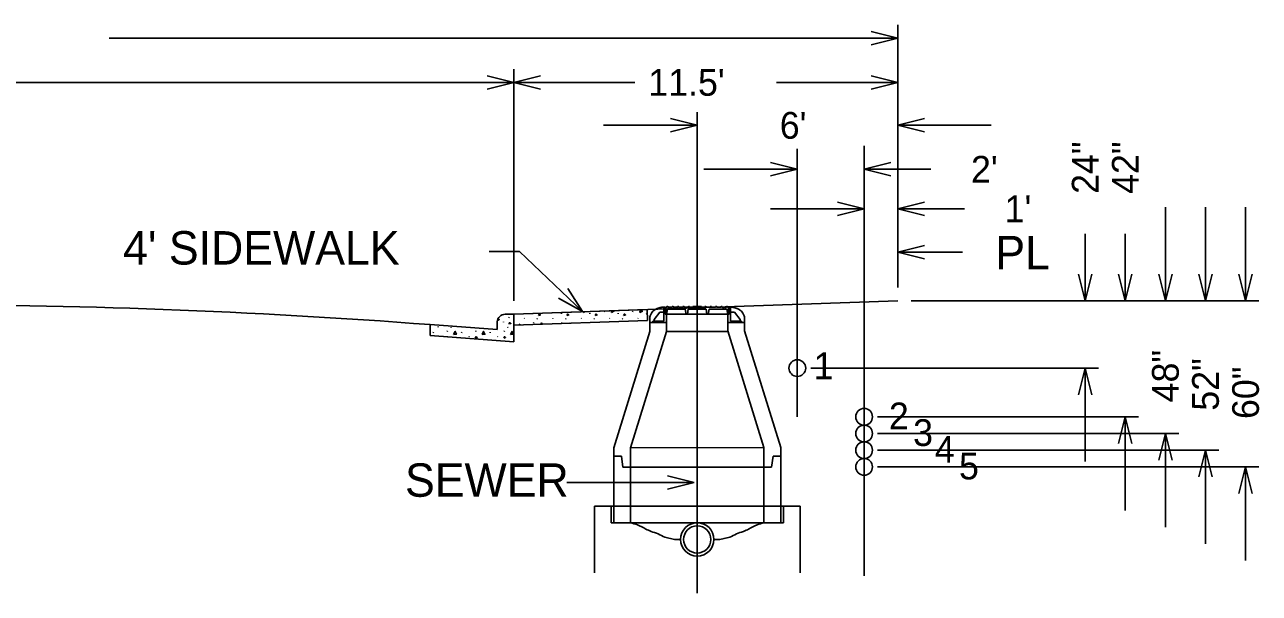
# Model space of a CAD drawing. Extents: x 524397 to 525117, y 3701341 to 3701821.
# Drawn here: x 524798.7 to 524872.7, y 3701503 to 3701537 of the extents above; entities that cross this region are included whole.
import ezdxf

# ---------------------------------------------------------------- set-up
doc = ezdxf.new("R2010")
doc.units = 0
doc.layers.add('Level 11', color=7, linetype='Continuous')

msp = doc.modelspace()

# ---------------------------------------------------------------- linework, layer by layer
at = {"layer": 'Level 11'}
for p, q in [((524851.022, 3701521.302), (524851.022, 3701537.038)), ((524849.421, 3701536.638), (524851.022, 3701536.238)), ((524803.793, 3701536.238), (524851.022, 3701536.238)), ((524851.022, 3701536.238), (524849.421, 3701535.838)), ((524828.022, 3701520.499), (524828.022, 3701534.384)), ((524851.022, 3701521.302), (524851.022, 3701534.384)), ((524793.673, 3701533.584), (524828.022, 3701533.584)), ((524826.421, 3701533.984), (524828.022, 3701533.584)), ((524828.022, 3701533.584), (524826.421, 3701533.183)), ((524828.022, 3701533.584), (524829.623, 3701533.984)), ((524835.28, 3701533.584), (524828.022, 3701533.584)), ((524829.623, 3701533.183), (524828.022, 3701533.584)), ((524843.764, 3701533.584), (524851.022, 3701533.584)), ((524849.421, 3701533.984), (524851.022, 3701533.584)), ((524851.022, 3701533.584), (524849.421, 3701533.183)), ((524837.407, 3701531.413), (524839.008, 3701531.013)), ((524839.008, 3701531.802), (524839.008, 3701502.983)), ((524851.022, 3701531.013), (524852.623, 3701531.413)), ((524833.405, 3701531.013), (524839.008, 3701531.013)), ((524839.008, 3701531.013), (524837.407, 3701530.613)), ((524856.626, 3701531.013), (524851.022, 3701531.013)), ((524852.623, 3701530.613), (524851.022, 3701531.013)), ((524845.008, 3701529.609), (524845.008, 3701513.548)), ((524849.008, 3701529.785), (524849.008, 3701504.024)), ((524839.405, 3701528.381), (524845.008, 3701528.381)), ((524843.407, 3701528.781), (524845.008, 3701528.381)), ((524845.008, 3701528.381), (524843.407, 3701527.981)), ((524849.008, 3701528.381), (524850.609, 3701528.781)), ((524853.011, 3701528.381), (524849.008, 3701528.381)), ((524850.609, 3701527.981), (524849.008, 3701528.381)), ((524843.405, 3701526.012), (524849.008, 3701526.012)), ((524847.407, 3701526.413), (524849.008, 3701526.012)), ((524849.008, 3701526.012), (524847.407, 3701525.612)), ((524851.022, 3701526.012), (524852.623, 3701526.413)), ((524855.025, 3701526.012), (524851.022, 3701526.012)), ((524852.623, 3701525.612), (524851.022, 3701526.012)), ((524867.055, 3701526.106), (524867.055, 3701520.502)), ((524869.456, 3701526.106), (524869.456, 3701520.502)), ((524871.858, 3701526.106), (524871.858, 3701520.502)), ((524862.252, 3701524.505), (524862.252, 3701520.502)), ((524864.653, 3701524.505), (524864.653, 3701520.502)), ((524851.022, 3701523.408), (524852.623, 3701523.808)), ((524828.357, 3701523.464), (524826.552, 3701523.464)), ((524832.135, 3701519.853), (524828.357, 3701523.464)), ((524851.022, 3701523.408), (524854.898, 3701523.408)), ((524852.623, 3701523.008), (524851.022, 3701523.408)), ((524862.252, 3701520.502), (524861.852, 3701522.103)), ((524862.652, 3701522.103), (524862.252, 3701520.502)), ((524864.653, 3701520.502), (524864.253, 3701522.103)), ((524865.054, 3701522.103), (524864.653, 3701520.502)), ((524867.055, 3701520.502), (524866.655, 3701522.103)), ((524867.455, 3701522.103), (524867.055, 3701520.502)), ((524869.456, 3701520.502), (524869.056, 3701522.103)), ((524869.856, 3701522.103), (524869.456, 3701520.502)), ((524871.858, 3701520.502), (524871.457, 3701522.103)), ((524872.258, 3701522.103), (524871.858, 3701520.502)), ((524831.254, 3701521.248), (524832.135, 3701519.853)), ((524828.022, 3701519.699), (524851.022, 3701520.502)), ((524832.135, 3701519.853), (524830.701, 3701520.669)), ((524837.009, 3701520.118), (524837.009, 3701520.118)), ((524837.009, 3701520.118), (524837.093, 3701520.118)), ((524837.009, 3701519.826), (524837.009, 3701520.118)), ((524837.093, 3701519.701), (524837.093, 3701520.118)), ((524837.134, 3701520.118), (524837.134, 3701519.701)), ((524837.177, 3701520.118), (524837.134, 3701520.118)), ((524837.176, 3701519.701), (524837.227, 3701519.993)), ((524837.177, 3701520.118), (524837.192, 3701520.159)), ((524837.192, 3701520.159), (524837.254, 3701520.159)), ((524838.29, 3701519.993), (524837.227, 3701519.993)), ((524837.269, 3701520.118), (524837.254, 3701520.159)), ((524837.501, 3701520.118), (524837.269, 3701520.118)), ((524837.501, 3701520.118), (524837.516, 3701520.159)), ((524837.516, 3701520.159), (524837.575, 3701520.159)), ((524837.59, 3701520.118), (524837.575, 3701520.159)), ((524837.817, 3701520.118), (524837.59, 3701520.118)), ((524837.817, 3701520.118), (524837.832, 3701520.159)), ((524837.832, 3701520.159), (524837.9, 3701520.159)), ((524837.915, 3701520.118), (524837.9, 3701520.159)), ((524838.144, 3701520.118), (524837.915, 3701520.118)), ((524838.144, 3701520.118), (524838.159, 3701520.159)), ((524838.159, 3701520.159), (524838.224, 3701520.159)), ((524838.24, 3701520.118), (524838.224, 3701520.159)), ((524838.467, 3701520.118), (524838.24, 3701520.118)), ((524838.342, 3701519.701), (524838.29, 3701519.993)), ((524838.425, 3701519.701), (524838.477, 3701519.993)), ((524838.467, 3701520.118), (524838.482, 3701520.159)), ((524839.54, 3701519.993), (524838.477, 3701519.993)), ((524838.482, 3701520.159), (524838.54, 3701520.159)), ((524838.555, 3701520.118), (524838.54, 3701520.159)), ((524838.742, 3701520.118), (524838.555, 3701520.118)), ((524838.742, 3701520.118), (524838.757, 3701520.159)), ((524838.757, 3701520.159), (524839.008, 3701520.159)), ((524839.259, 3701520.159), (524839.008, 3701520.159)), ((524839.275, 3701520.118), (524839.259, 3701520.159)), ((524839.461, 3701520.118), (524839.275, 3701520.118)), ((524839.461, 3701520.118), (524839.476, 3701520.159)), ((524839.535, 3701520.159), (524839.476, 3701520.159)), ((524839.55, 3701520.118), (524839.535, 3701520.159)), ((524839.591, 3701519.701), (524839.54, 3701519.993)), ((524839.777, 3701520.118), (524839.55, 3701520.118)), ((524839.674, 3701519.701), (524839.725, 3701519.993)), ((524840.789, 3701519.993), (524839.725, 3701519.993)), ((524839.777, 3701520.118), (524839.792, 3701520.159)), ((524839.857, 3701520.159), (524839.792, 3701520.159)), ((524839.873, 3701520.118), (524839.857, 3701520.159)), ((524840.101, 3701520.118), (524839.873, 3701520.118)), ((524840.101, 3701520.118), (524840.116, 3701520.159)), ((524840.185, 3701520.159), (524840.116, 3701520.159)), ((524840.199, 3701520.118), (524840.185, 3701520.159)), ((524840.426, 3701520.118), (524840.199, 3701520.118)), ((524840.426, 3701520.118), (524840.441, 3701520.159)), ((524840.5, 3701520.159), (524840.441, 3701520.159)), ((524840.515, 3701520.118), (524840.5, 3701520.159)), ((524840.747, 3701520.118), (524840.515, 3701520.118)), ((524840.57, 3701520.118), (524840.57, 3701519.993)), ((524840.695, 3701520.118), (524840.695, 3701519.993)), ((524840.747, 3701520.118), (524840.762, 3701520.159)), ((524840.825, 3701520.159), (524840.762, 3701520.159)), ((524840.841, 3701519.701), (524840.789, 3701519.993)), ((524840.84, 3701520.118), (524840.825, 3701520.159)), ((524840.881, 3701520.118), (524840.84, 3701520.118)), ((524840.881, 3701520.118), (524840.881, 3701519.701)), ((524840.924, 3701519.701), (524840.923, 3701520.118)), ((524841.007, 3701520.118), (524840.923, 3701520.118)), ((524841.007, 3701519.826), (524841.007, 3701520.118)), ((524851.823, 3701520.502), (524863.052, 3701520.502)), ((524851.823, 3701520.502), (524865.454, 3701520.502)), ((524851.823, 3701520.502), (524867.855, 3701520.502)), ((524851.823, 3701520.502), (524870.257, 3701520.502)), ((524851.823, 3701520.502), (524872.658, 3701520.502)), ((524827.411, 3701519.251), (524827.415, 3701519.219)), ((524828.022, 3701519.699), (524827.509, 3701519.699)), ((524827.509, 3701519.699), (524827.522, 3701519.699)), ((524827.728, 3701519.486), (524827.743, 3701519.517)), ((524828.022, 3701519.699), (524836.017, 3701519.978)), ((524828.022, 3701518.037), (524828.022, 3701519.699)), ((524828.022, 3701519.039), (524828.022, 3701519.699)), ((524836.041, 3701519.319), (524828.022, 3701519.039)), ((524828.655, 3701519.433), (524828.669, 3701519.465)), ((524829.178, 3701519.739), (524829.18, 3701519.724)), ((524829.419, 3701519.433), (524829.433, 3701519.412)), ((524829.433, 3701519.425), (524829.447, 3701519.404)), ((524830.356, 3701519.433), (524830.371, 3701519.465)), ((524830.878, 3701519.756), (524830.881, 3701519.724)), ((524831.12, 3701519.433), (524831.134, 3701519.412)), ((524831.134, 3701519.425), (524831.149, 3701519.404)), ((524832.058, 3701519.433), (524832.072, 3701519.465)), ((524832.579, 3701519.756), (524832.583, 3701519.724)), ((524832.822, 3701519.433), (524832.836, 3701519.412)), ((524832.836, 3701519.425), (524832.85, 3701519.404)), ((524833.436, 3701519.845), (524833.45, 3701519.877)), ((524833.759, 3701519.433), (524833.774, 3701519.465)), ((524834.281, 3701519.756), (524834.284, 3701519.724)), ((524834.523, 3701519.433), (524834.537, 3701519.412)), ((524834.537, 3701519.425), (524834.552, 3701519.404)), ((524835.138, 3701519.845), (524835.152, 3701519.877)), ((524835.461, 3701519.433), (524835.475, 3701519.465)), ((524835.982, 3701519.756), (524835.986, 3701519.724)), ((524836.017, 3701519.978), (524836.041, 3701519.319)), ((524836.343, 3701519.201), (524836.343, 3701519.285)), ((524836.343, 3701519.285), (524836.427, 3701519.285)), ((524836.427, 3701519.389), (524836.777, 3701519.827)), ((524836.427, 3701519.285), (524836.427, 3701519.389)), ((524836.427, 3701519.285), (524837.009, 3701519.285)), ((524836.777, 3701519.827), (524837.009, 3701519.826)), ((524837.009, 3701519.285), (524837.009, 3701519.826)), ((524837.176, 3701519.701), (524837.093, 3701519.701)), ((524837.134, 3701519.701), (524840.881, 3701519.701)), ((524837.176, 3701519.201), (524837.176, 3701519.701)), ((524840.841, 3701519.201), (524840.841, 3701519.701)), ((524840.841, 3701519.701), (524840.924, 3701519.701)), ((524841.24, 3701519.827), (524841.007, 3701519.826)), ((524841.007, 3701519.285), (524841.007, 3701519.826)), ((524841.59, 3701519.285), (524841.007, 3701519.285)), ((524841.59, 3701519.389), (524841.24, 3701519.827)), ((524841.59, 3701519.285), (524841.59, 3701519.389)), ((524841.673, 3701519.285), (524841.59, 3701519.285)), ((524841.673, 3701519.201), (524841.673, 3701519.285)), ((524827.022, 3701518.774), (524823.022, 3701519.076)), ((524823.022, 3701519.076), (524823.022, 3701518.415)), ((524823.199, 3701518.583), (524823.213, 3701518.615)), ((524823.487, 3701518.928), (524823.501, 3701518.96)), ((524824.041, 3701518.665), (524824.055, 3701518.697)), ((524824.251, 3701518.928), (524824.265, 3701518.907)), ((524824.265, 3701518.92), (524824.279, 3701518.898)), ((524824.901, 3701518.583), (524824.915, 3701518.615)), ((524825.743, 3701518.665), (524825.757, 3701518.697)), ((524826.602, 3701518.583), (524826.616, 3701518.615)), ((524827.022, 3701519.237), (524827.022, 3701518.774)), ((524827.444, 3701518.665), (524827.458, 3701518.697)), ((524827.654, 3701518.928), (524827.668, 3701518.907)), ((524827.668, 3701518.92), (524827.682, 3701518.898)), ((524828.367, 3701519.088), (524828.381, 3701519.12)), ((524829.209, 3701519.17), (524829.223, 3701519.202)), ((524830.079, 3701519.111), (524830.083, 3701519.12)), ((524830.911, 3701519.17), (524830.925, 3701519.202)), ((524832.625, 3701519.199), (524832.626, 3701519.202)), ((524836.166, 3701518.668), (524834.016, 3701511.701)), ((524837.166, 3701518.669), (524835.015, 3701511.702)), ((524836.166, 3701519.201), (524836.166, 3701518.668)), ((524836.166, 3701519.201), (524836.343, 3701519.201)), ((524837.176, 3701519.201), (524836.166, 3701519.201)), ((524837.166, 3701518.669), (524837.166, 3701519.201)), ((524837.166, 3701519.035), (524837.166, 3701518.709)), ((524837.166, 3701518.669), (524840.851, 3701518.669)), ((524841.851, 3701519.201), (524840.841, 3701519.201)), ((524840.851, 3701519.201), (524840.851, 3701518.702)), ((524841.851, 3701519.201), (524840.851, 3701519.201)), ((524840.851, 3701518.868), (524840.851, 3701519.042)), ((524840.851, 3701518.702), (524843.01, 3701511.706)), ((524841.851, 3701519.201), (524841.673, 3701519.201)), ((524841.85, 3701518.702), (524841.85, 3701519.201)), ((524841.85, 3701518.702), (524844.01, 3701511.706)), ((524823.022, 3701518.415), (524828.022, 3701518.037)), ((524825.345, 3701518.356), (524825.359, 3701518.334)), ((524827.046, 3701518.356), (524827.06, 3701518.334)), ((524845.809, 3701516.472), (524863.052, 3701516.472)), ((524861.852, 3701514.871), (524862.252, 3701516.472)), ((524862.252, 3701510.868), (524862.252, 3701516.472)), ((524862.252, 3701516.472), (524862.652, 3701514.871)), ((524849.809, 3701513.552), (524865.454, 3701513.552)), ((524864.253, 3701511.951), (524864.653, 3701513.552)), ((524864.653, 3701507.948), (524864.653, 3701513.552)), ((524864.653, 3701513.552), (524865.054, 3701511.951)), ((524849.809, 3701512.552), (524867.855, 3701512.552)), ((524866.655, 3701510.951), (524867.055, 3701512.552)), ((524867.055, 3701506.948), (524867.055, 3701512.552)), ((524867.055, 3701512.552), (524867.455, 3701510.951)), ((524834.016, 3701511.701), (524834.016, 3701510.54)), ((524834.016, 3701511.408), (524834.016, 3701511.206)), ((524834.016, 3701511.206), (524834.474, 3701511.206)), ((524834.016, 3701511.206), (524834.474, 3701511.206)), ((524834.016, 3701511.206), (524834.016, 3701509.819)), ((524834.474, 3701511.206), (524834.557, 3701510.54)), ((524834.474, 3701511.206), (524834.557, 3701510.54)), ((524843.01, 3701511.706), (524835.015, 3701511.702)), ((524835.015, 3701510.54), (524835.015, 3701511.702)), ((524835.015, 3701511.206), (524835.015, 3701511.408)), ((524835.015, 3701509.819), (524835.015, 3701511.206)), ((524843.01, 3701511.706), (524843.01, 3701510.54)), ((524843.01, 3701511.706), (524843.01, 3701511.206)), ((524843.01, 3701511.408), (524843.01, 3701511.206)), ((524843.01, 3701511.408), (524843.01, 3701511.206)), ((524843.01, 3701511.206), (524843.01, 3701507.209)), ((524843.01, 3701511.206), (524843.01, 3701507.209)), ((524843.468, 3701510.54), (524843.552, 3701511.206)), ((524843.468, 3701510.54), (524843.552, 3701511.206)), ((524843.552, 3701511.206), (524844.01, 3701511.206)), ((524843.552, 3701511.206), (524844.01, 3701511.206)), ((524843.552, 3701511.206), (524844.01, 3701511.206)), ((524844.01, 3701511.206), (524844.01, 3701511.706)), ((524844.01, 3701511.206), (524844.01, 3701511.706)), ((524844.01, 3701507.209), (524844.01, 3701511.408)), ((524844.01, 3701510.54), (524844.01, 3701511.206)), ((524849.809, 3701511.552), (524870.257, 3701511.552)), ((524869.056, 3701509.951), (524869.456, 3701511.552)), ((524869.456, 3701505.948), (524869.456, 3701511.552)), ((524869.456, 3701511.552), (524869.856, 3701509.951)), ((524834.016, 3701510.818), (524834.016, 3701507.209)), ((524834.557, 3701510.54), (524835.015, 3701510.54)), ((524834.557, 3701510.54), (524835.015, 3701510.54)), ((524835.015, 3701510.54), (524843.01, 3701510.54)), ((524835.015, 3701510.54), (524843.01, 3701510.54)), ((524843.01, 3701510.54), (524843.468, 3701510.54)), ((524843.01, 3701510.54), (524843.468, 3701510.54)), ((524849.809, 3701510.552), (524872.658, 3701510.552)), ((524871.457, 3701508.951), (524871.858, 3701510.552)), ((524871.858, 3701504.948), (524871.858, 3701510.552)), ((524871.858, 3701510.552), (524872.258, 3701508.951)), ((524835.015, 3701509.819), (524835.015, 3701508.635)), ((524837.223, 3701510.016), (524838.824, 3701509.616)), ((524838.824, 3701509.616), (524831.206, 3701509.616)), ((524838.824, 3701509.616), (524837.223, 3701509.216)), ((524834.016, 3701508.208), (524832.85, 3701508.208)), ((524832.85, 3701508.208), (524832.85, 3701504.211)), ((524833.849, 3701507.209), (524833.849, 3701508.208)), ((524834.016, 3701508.208), (524844.01, 3701508.208)), ((524835.015, 3701507.209), (524835.015, 3701508.635)), ((524844.01, 3701508.208), (524845.176, 3701508.208)), ((524844.176, 3701507.209), (524844.176, 3701508.208)), ((524845.176, 3701508.208), (524845.176, 3701504.211)), ((524834.016, 3701507.209), (524833.849, 3701507.209)), ((524834.016, 3701507.209), (524833.849, 3701507.209)), ((524834.016, 3701507.209), (524835.015, 3701507.209)), ((524835.015, 3701507.209), (524834.016, 3701507.209)), ((524835.015, 3701507.209), (524834.016, 3701507.209)), ((524835.015, 3701507.209), (524843.01, 3701507.209)), ((524843.01, 3701507.209), (524844.01, 3701507.209)), ((524843.01, 3701507.209), (524844.01, 3701507.209)), ((524844.01, 3701507.209), (524844.176, 3701507.209))]:
    msp.add_line(p, q, dxfattribs=at)
for points in [[(524837.134, 3701520.118), (524837.177, 3701520.118), (524837.192, 3701520.159), (524837.254, 3701520.159), (524837.269, 3701520.118), (524837.501, 3701520.118), (524837.516, 3701520.159), (524837.575, 3701520.159), (524837.59, 3701520.118), (524837.817, 3701520.118), (524837.832, 3701520.159), (524837.9, 3701520.159), (524837.915, 3701520.118), (524838.144, 3701520.118), (524838.159, 3701520.159), (524838.224, 3701520.159), (524838.24, 3701520.118), (524838.467, 3701520.118), (524838.482, 3701520.159), (524838.54, 3701520.159), (524838.555, 3701520.118), (524838.742, 3701520.118), (524838.757, 3701520.159), (524839.259, 3701520.159), (524839.275, 3701520.118), (524839.461, 3701520.118), (524839.476, 3701520.159), (524839.535, 3701520.159), (524839.55, 3701520.118), (524839.777, 3701520.118), (524839.792, 3701520.159), (524839.857, 3701520.159), (524839.873, 3701520.118), (524840.101, 3701520.118), (524840.116, 3701520.159), (524840.185, 3701520.159), (524840.199, 3701520.118), (524840.426, 3701520.118), (524840.441, 3701520.159), (524840.5, 3701520.159), (524840.515, 3701520.118), (524840.57, 3701520.118), (524840.57, 3701519.993), (524839.725, 3701519.993), (524839.674, 3701519.701), (524839.591, 3701519.701), (524839.54, 3701519.993), (524838.477, 3701519.993), (524838.425, 3701519.701), (524838.342, 3701519.701), (524838.29, 3701519.993), (524837.227, 3701519.993), (524837.176, 3701519.701), (524837.134, 3701519.701)], [(524840.695, 3701520.118), (524840.747, 3701520.118), (524840.762, 3701520.159), (524840.825, 3701520.159), (524840.84, 3701520.118), (524840.881, 3701520.118), (524840.881, 3701519.701), (524840.841, 3701519.701), (524840.789, 3701519.993), (524840.695, 3701519.993)]]:
    msp.add_lwpolyline(points, close=True, dxfattribs=at)
for points in [[(524827.086, 3701519.445), (524827.154, 3701519.375), (524827.05, 3701519.326)], [(524829.5, 3701519.618), (524829.543, 3701519.707), (524829.614, 3701519.653), (524829.5, 3701519.618)], [(524831.202, 3701519.618), (524831.245, 3701519.707), (524831.316, 3701519.653), (524831.202, 3701519.618)], [(524832.167, 3701519.808), (524832.172, 3701519.844)], [(524832.25, 3701519.847), (524832.17, 3701519.81)], [(524832.903, 3701519.618), (524832.946, 3701519.707), (524833.017, 3701519.653), (524832.903, 3701519.618)], [(524833.868, 3701519.808), (524833.882, 3701519.904)], [(524833.997, 3701519.908), (524834.024, 3701519.88), (524833.872, 3701519.81)], [(524834.605, 3701519.618), (524834.648, 3701519.707), (524834.719, 3701519.653), (524834.605, 3701519.618)], [(524835.57, 3701519.808), (524835.591, 3701519.963)], [(524835.643, 3701519.965), (524835.725, 3701519.88), (524835.573, 3701519.81)], [(524824.421, 3701518.487), (524824.517, 3701518.668), (524824.592, 3701518.501), (524824.425, 3701518.487)], [(524826.123, 3701518.487), (524826.219, 3701518.668), (524826.293, 3701518.501), (524826.126, 3701518.487)], [(524827.735, 3701519.113), (524827.778, 3701519.201), (524827.849, 3701519.148), (524827.735, 3701519.113)], [(524827.824, 3701518.487), (524827.92, 3701518.668), (524827.995, 3701518.501), (524827.828, 3701518.487)], [(524828.022, 3701519.087), (524828.043, 3701519.039)], [(524829.644, 3701519.095), (524829.685, 3701519.173), (524829.719, 3701519.098)], [(524831.377, 3701519.156), (524831.387, 3701519.173), (524831.394, 3701519.156)], [(524824.052, 3701518.337), (524824.059, 3701518.352), (524824.082, 3701518.335)], [(524825.718, 3701518.263), (524825.76, 3701518.352), (524825.831, 3701518.299), (524825.718, 3701518.263)], [(524827.419, 3701518.263), (524827.462, 3701518.352), (524827.533, 3701518.299), (524827.419, 3701518.263)]]:
    msp.add_lwpolyline(points, dxfattribs=at)
for centre, radius in [((524845.008, 3701516.472), 0.5), ((524849.008, 3701513.552), 0.5), ((524849.008, 3701512.552), 0.5), ((524849.008, 3701511.552), 0.5), ((524849.008, 3701510.552), 0.5), ((524839.013, 3701506.209), 0.999), ((524839.013, 3701506.209), 0.814)]:
    msp.add_circle(centre, radius, dxfattribs=at)
for centre, radius, start, end in [((524791.02, 3701095.204), 425.079, 85.68236, 94.31764), ((524827.516, 3701519.205), 0.494, 89.23325, 176.29205)]:
    msp.add_arc(centre, radius, start, end, dxfattribs=at)
for points in [[(524837.009, 3701520.118), (524836.936, 3701520.117), (524836.857, 3701520.106), (524836.788, 3701520.094), (524836.729, 3701520.082), (524836.666, 3701520.054), (524836.607, 3701520.041), (524836.464, 3701519.961), (524836.361, 3701519.876), (524836.269, 3701519.757), (524836.193, 3701519.593), (524836.173, 3701519.361), (524836.166, 3701519.201)], [(524841.007, 3701520.118), (524841.08, 3701520.117), (524841.159, 3701520.106), (524841.228, 3701520.094), (524841.286, 3701520.082), (524841.35, 3701520.054), (524841.409, 3701520.041), (524841.552, 3701519.961), (524841.656, 3701519.876), (524841.747, 3701519.757), (524841.823, 3701519.593), (524841.844, 3701519.361), (524841.85, 3701519.201)], [(524835.015, 3701507.209), (524835.429, 3701507.084), (524835.933, 3701506.833), (524836.248, 3701506.686), (524836.668, 3701506.539), (524837.067, 3701506.351), (524837.403, 3701506.267), (524837.738, 3701506.204), (524838.013, 3701506.209)], [(524843.01, 3701507.209), (524842.596, 3701507.084), (524842.092, 3701506.833), (524841.777, 3701506.686), (524841.358, 3701506.539), (524840.959, 3701506.351), (524840.623, 3701506.267), (524840.286, 3701506.204), (524840.012, 3701506.209)]]:
    msp.add_spline(points, degree=3, dxfattribs=at)

# ---------------------------------------------------------------- texts
for s, height, p in [("11.5'", 1.601, (524836.081, 3701532.783)), ("6'", 1.601, (524843.956, 3701530.211)), ("2'", 1.601, (524855.412, 3701527.579)), ("1'", 1.601, (524857.426, 3701525.211)), ("4' SIDEWALK", 2, (524804.621, 3701522.673)), ('PL', 2, (524856.868, 3701522.39)), ('1', 1.601, (524845.988, 3701515.807)), ('2', 1.601, (524850.494, 3701512.807)), ('3', 1.601, (524851.944, 3701511.807)), ('4', 1.601, (524853.242, 3701510.807)), ('5', 1.601, (524854.693, 3701509.807)), ('SEWER', 2, (524821.507, 3701508.765))]:
    msp.add_text(s, height=height, dxfattribs=at).set_placement(p)
for s, p in [('24"', (524863.052, 3701526.905)), ('42"', (524865.454, 3701526.905)), ('48"', (524867.855, 3701514.42)), ('52"', (524870.257, 3701513.92)), ('60"', (524872.658, 3701513.42))]:
    msp.add_text(s, height=1.601, rotation=90, dxfattribs=at).set_placement(p)

doc.saveas('drawing.dxf')
